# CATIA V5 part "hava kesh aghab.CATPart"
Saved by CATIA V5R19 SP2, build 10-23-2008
Part number: hava kesh aghab
Bounding box of the stored display mesh (mm): x -1378.013 to -1124.461, y -164.677 to 164.677, z 64.318 to 348.418
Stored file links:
  C:\BEHROOZ\catia learning\tarh haye mashin\hb\hava kesh aghab.CATPart
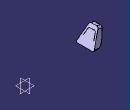
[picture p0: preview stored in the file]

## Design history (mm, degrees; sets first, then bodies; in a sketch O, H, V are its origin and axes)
Body1 (main body)
  DatumSurface1
  DatumSurface2
  Sketch1 on zx-plane, origin (0, 0, 0), H (-1, 0, 0), V (0, 0, 1)
    line L1 (1299.866, 348.4176) -> (1407.8202, 325.1046)
    arc A1 centre (-795.0911, 792.2625) radius 2251.9002 from (1407.8202, 325.1046) to (1335.7062, 63.7313) cw
    line L2 (1335.7062, 63.7313) -> (1124.461, 64.8467)
    line L3 (1124.461, 64.8467) -> (1299.866, 348.4176)
  Pad1: profile Sketch1, direction (0, 1, 0), length 171, mirrored extent
  DatumSurface3 to DatumSurface9
  Join1: Elements (DatumSurface3; DatumSurface4; DatumSurface5; DatumSurface6; DatumSurface7; DatumSurface8; DatumSurface9)
  Translate1: ToTransfor Join1, Direction (1, 0, 0), Length -53
  Plane1: stored without definition
  Split1: SplitPlane Translate1
  Sketch2 on Plane1, origin (-1447, 0, 0), H (0, 1, 0), V (0, 0, 1)
    line L1 (-171, 64.392) -> (-76.1471, 363.2289)
    line L2 (-76.1471, 363.2289) -> (-277.594, 373.7312)
    line L3 (-277.594, 373.7312) -> (-293.7211, 64.392)
    line L4 (-293.7211, 64.392) -> (-171, 64.392)
    line L5 (171, 64.392) -> (76.1471, 363.2289)
    line L6 (76.1471, 363.2289) -> (277.594, 373.7312)
    line L7 (277.594, 373.7312) -> (293.7211, 64.392)
    line L8 (293.7211, 64.392) -> (171, 64.392)
  Pocket1: profile Sketch2, direction (-1, 0, 0), length -249
  Plane2: stored without definition
  Plane3: stored without definition
  Fillet1: radius 40, on edge [face of Pad1 from Sketch1.L1 | face of Pocket1 from Sketch2.L1]; edge [face of Pocket1 from Sketch2.L5 | face of Pad1 from Sketch1.L1]
  Sketch3 on Plane3, origin (-1447, 0, 0), H (0, 1, 0), V (0, 0, 1)
    line L1 (-136.0182, 64.2243) -> (-68.2947, 273.0876)
    line L2 (-44.5136, 290.3766) -> (0, 290.3766)
    point P2 (0, 290.3766)
    line L3 (136.0182, 64.2243) -> (68.2947, 273.0876)
    point P4 (0, 290.3766)
    line L4 (44.5136, 290.3766) -> (0, 290.3766)
    arc A1 centre (-44.5136, 265.3766) radius 25 from (-44.5136, 290.3766) to (-68.2947, 273.0876) ccw
    arc A2 centre (44.5136, 265.3766) radius 25 from (44.5136, 290.3766) to (68.2947, 273.0876) cw
    coincidence: P2 P4
  Fillet2: radius 69, on edge [face of Split1 | face of Pad1 from Sketch1.L2]
  Pocket2: profile Sketch3, direction (-1, 0, 0), length -249, thin wall 0, second thickness 1
  Chamfer1: length 21, angle 45, on edge [face of Pad1 from Sketch1.L1 | face of Split1]
  Plane4: stored without definition
  Sketch4 on end face of Pocket1, origin (-1198, 0, 0), H (0, -1, 0), V (0, 0, 1)
  Pocket3: profile Sketch4, direction (-1, 0, 0), length -249
  Join2: Elements (face of Split1; face of Split1; face of Fillet2)
  DatumCurve1
  Translate2: Direction DatumCurve1, Length 11, ToTransfor Join2
  Split2: SplitPlane Translate2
